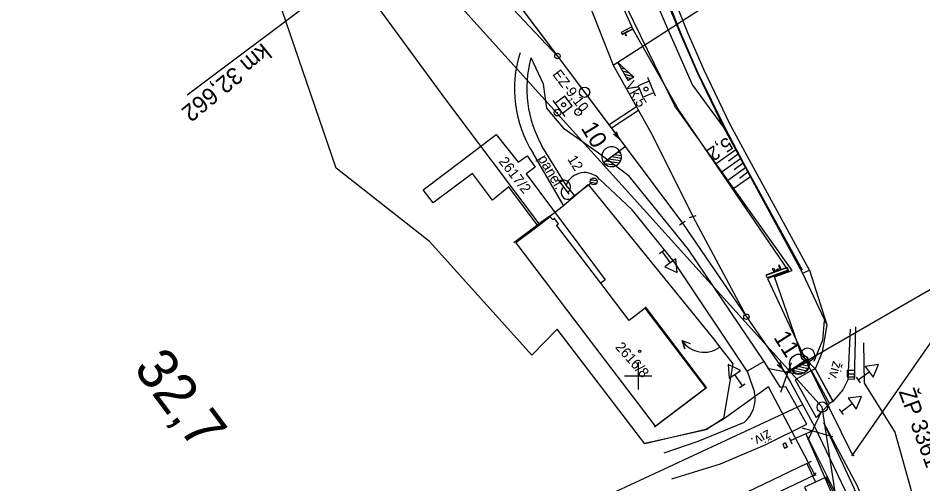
# Model space of a CAD drawing. Extents: x -804166 to -803706, y -1151030 to -1150147.
# Drawn here: x -803991 to -803858.2, y -1150515.9 to -1150447.5 of the extents above; entities that cross this region are included whole.
import ezdxf

# ---------------------------------------------------------------- set-up
doc = ezdxf.new("R2010")
doc.units = 0
for name, color, linetype in [('0381KM032-037P - Vrstva 1', 7, 'Continuous'), ('0381KM032-037P - Vrstva 12', 7, 'Continuous'), ('0381KM032-037P - Vrstva 13', 7, 'Continuous'), ('0381KM032-037P - Vrstva 17', 7, 'Continuous'), ('0381KM032-037P - Vrstva 19', 7, 'Continuous'), ('0381KM032-037P - Vrstva 2', 7, 'Continuous'), ('0381KM032-037P - Vrstva 23', 7, 'Continuous'), ('0381KM032-037P - Vrstva 25', 7, 'Continuous'), ('0381KM032-037P - Vrstva 27', 7, 'Continuous'), ('0381KM032-037P - Vrstva 3', 7, 'Continuous'), ('0381KM032-037P - Vrstva 4', 7, 'Continuous'), ('0381KM032-037P - Vrstva 43', 7, 'Continuous'), ('0381KM032-037P - Vrstva 48', 7, 'Continuous'), ('0381KM032-037P - Vrstva 49', 7, 'Continuous'), ('0381KM032-037P - Vrstva 5', 7, 'Continuous'), ('0381KM032-037P - Vrstva 51', 7, 'Continuous'), ('0381KM032-037P - Vrstva 55', 7, 'Continuous'), ('0381KM032-037P - Vrstva 57', 7, 'Continuous'), ('0381KM032-037P - Vrstva 59', 7, 'Continuous'), ('0381KM032-037P - Vrstva 6', 7, 'Continuous'), ('0381KM032-037P - Vrstva 7', 7, 'Continuous'), ('hran DP - hran DP', 7, 'Continuous'), ('krizky_1000 - Vrstva 1', 7, 'Continuous'), ('vyt_sit - polygon', 7, 'Continuous'), ('vyt_sit - stávající', 7, 'Continuous')]:
    doc.layers.add(name, color=color, linetype=linetype)

msp = doc.modelspace()

# ---------------------------------------------------------------- linework, layer by layer
at = {"layer": '0381KM032-037P - Vrstva 1'}
msp.add_line((-803901.9, -1150466.33), (-803893.52, -1150477.59), dxfattribs=at)
for points in [[(-804011.14, -1150262.39), (-804005.45, -1150273.41), (-803998.73, -1150284.85), (-803991.51, -1150295.63), (-803978.8, -1150312.77), (-803963.69, -1150332.99), (-803952.21, -1150348.36), (-803946.3, -1150356.39), (-803941.6, -1150363.14), (-803936.71, -1150370.83), (-803932.05, -1150378.84), (-803927.78, -1150386.91), (-803924.06, -1150395.18), (-803920.62, -1150403.65), (-803918.06, -1150410.86), (-803915.07, -1150420.32), (-803912.96, -1150427.25), (-803910.49, -1150435.34), (-803907.33, -1150445.05), (-803903.67, -1150454.38), (-803897.94, -1150464.6), (-803891.97, -1150476.6)], [(-803975.62, -1150392.3), (-803939.47, -1150444.12), (-803928.27, -1150459.42), (-803914.53, -1150477.73)], [(-803921.85, -1150439.73), (-803911.86, -1150453.03), (-803902.83, -1150465.07), (-803901.9, -1150466.33)], [(-803923.25, -1150440.92), (-803911.86, -1150453.03), (-803902.83, -1150465.07), (-803901.9, -1150466.33)], [(-803891.97, -1150476.6), (-803884.11, -1150491.33), (-803878.84, -1150498.97), (-803878.44, -1150499.6)], [(-803893.52, -1150477.59), (-803884.11, -1150491.33), (-803878.84, -1150498.97), (-803878.44, -1150499.6)], [(-803878.44, -1150499.6), (-803877.66, -1150500.95), (-803874.07, -1150507.54)], [(-803874.07, -1150507.54), (-803869.67, -1150516.77), (-803865.8, -1150526.59), (-803862.65, -1150536.71)]]:
    msp.add_lwpolyline(points, dxfattribs=at)
at = {"layer": '0381KM032-037P - Vrstva 12'}
for q in [(-803878.79, -1150510.04), (-803878.4, -1150509.87), (-803878.14, -1150510.46)]:
    msp.add_line((-803878.39, -1150509.85), q, dxfattribs=at)
for points in [[(-803878.4, -1150509.87), (-803878.79, -1150510.05), (-803878.52, -1150510.62), (-803878.14, -1150510.45), (-803878.4, -1150509.87)], [(-803878.79, -1150510.05), (-803878.79, -1150510.04), (-803878.54, -1150510.62), (-803878.52, -1150510.62)], [(-803878.54, -1150510.62), (-803878.14, -1150510.46), (-803878.14, -1150510.45)]]:
    msp.add_lwpolyline(points, dxfattribs=at)
at = {"layer": '0381KM032-037P - Vrstva 13'}
msp.add_lwpolyline([(-803875.88, -1150484.91), (-803874.86, -1150484.5), (-803883.66, -1150468.35), (-803886.5, -1150463.09), (-803890.34, -1150455.1), (-803892.74, -1150449.64), (-803894.89, -1150444.21), (-803895.92, -1150441.28), (-803896.68, -1150438.64), (-803897.15, -1150435.87), (-803897.2, -1150433.43), (-803898.65, -1150433.26), (-803898.54, -1150435.86), (-803897.99, -1150438.86), (-803897.04, -1150441.74), (-803895.99, -1150444.53), (-803893.7, -1150450.06), (-803891.29, -1150455.54), (-803887.41, -1150463.6)], close=True, dxfattribs=at)
at = {"layer": '0381KM032-037P - Vrstva 17'}
for p, q in [((-803911.21, -1150475.17), (-803907.34, -1150471.9)), ((-803888.96, -1150494.57), (-803888.03, -1150495.78))]:
    msp.add_line(p, q, dxfattribs=at)
for points in [[(-803875.87, -1150484.46), (-803884.49, -1150468.8), (-803887.25, -1150463.57), (-803891.19, -1150455.53), (-803893.61, -1150450.03), (-803895.79, -1150444.44), (-803896.9, -1150441.76), (-803897.82, -1150438.89), (-803898.31, -1150435.88), (-803898.26, -1150432.78)], [(-803907.34, -1150471.9), (-803888.96, -1150494.57)], [(-803912.99, -1150476.53), (-803911.21, -1150475.17)], [(-803872.72, -1150491.9), (-803872.97, -1150494.74), (-803874.21, -1150497.92)], [(-803888.03, -1150495.78), (-803886.13, -1150498.24), (-803887.49, -1150506.28), (-803890.05, -1150507.93), (-803899.02, -1150509.95)]]:
    msp.add_lwpolyline(points, dxfattribs=at)
at = {"layer": '0381KM032-037P - Vrstva 19'}
for p, q in [((-803902.47, -1150449.51), (-803900.98, -1150448.74)), ((-803900.83, -1150449.07), (-803902.37, -1150449.82)), ((-803902.35, -1150449.88), (-803900.83, -1150449.07)), ((-803900.98, -1150448.74), (-803900.83, -1150449.07)), ((-803902.37, -1150449.82), (-803902.47, -1150449.51)), ((-803902.37, -1150449.82), (-803902.35, -1150449.88)), ((-803901.82, -1150450), (-803901.91, -1150449.7)), ((-803881.21, -1150485.2), (-803878.12, -1150484.1)), ((-803877.97, -1150484.47), (-803881.05, -1150485.62)), ((-803879.4, -1150483.82), (-803879.16, -1150484.36)), ((-803879.16, -1150484.36), (-803879.02, -1150484.39)), ((-803878.12, -1150484.1), (-803877.97, -1150484.47)), ((-803881.05, -1150485.62), (-803881.21, -1150485.2))]:
    msp.add_line(p, q, dxfattribs=at)
for points in [[(-803900.83, -1150449.07), (-803900.83, -1150449.07), (-803900.77, -1150449.2)], [(-803901.91, -1150449.7), (-803901.91, -1150449.66), (-803901.71, -1150450.07), (-803901.82, -1150450)], [(-803878.12, -1150484.1), (-803878.12, -1150484.1), (-803881.19, -1150485.17), (-803881.21, -1150485.2)], [(-803880.09, -1150484.18), (-803879.84, -1150484.69), (-803880.02, -1150484.66), (-803880.28, -1150484.3), (-803880.09, -1150484.18)], [(-803879.02, -1150484.39), (-803879.24, -1150483.75), (-803879.4, -1150483.82)]]:
    msp.add_lwpolyline(points, dxfattribs=at)
for centre, major_axis, ratio in [((-803901.56, -1150449.43), (0.129, 0.077), 0.428282), ((-803879.58, -1150484.39), (-0.127, -0.08), 0.380929)]:
    msp.add_ellipse(centre, major_axis=major_axis, ratio=ratio, dxfattribs=at)
at = {"layer": '0381KM032-037P - Vrstva 2'}
for p, q in [((-803921.85, -1150439.73), (-803911.86, -1150453.03)), ((-803905.08, -1150468.69), (-803901.9, -1150466.33)), ((-803905.08, -1150468.69), (-803902.73, -1150466.95)), ((-803902.45, -1150467.68), (-803903.5, -1150467.52)), ((-803902.55, -1150467.28), (-803903.07, -1150467.2)), ((-803905.08, -1150468.69), (-803905.08, -1150468.69)), ((-803903.2, -1150469.1), (-803904.95, -1150468.84)), ((-803902.8, -1150468.78), (-803904.8, -1150468.48)), ((-803902.58, -1150468.42), (-803904.37, -1150468.16)), ((-803902.47, -1150468.06), (-803903.93, -1150467.84)), ((-803878.44, -1150499.6), (-803834.82, -1150474.4)), ((-803892.45, -1150476.74), (-803891.49, -1150476.45)), ((-803891.97, -1150476.6), (-803884.11, -1150491.33)), ((-803893.09, -1150477.33), (-803893.95, -1150477.85)), ((-803877.57, -1150499.05), (-803875.11, -1150497.47)), ((-803876.32, -1150498.25), (-803874.91, -1150498.56)), ((-803875.87, -1150497.96), (-803874.88, -1150498.18)), ((-803875.43, -1150497.68), (-803874.96, -1150497.78)), ((-803877.58, -1150499.05), (-803878.44, -1150499.6)), ((-803877.57, -1150499.05), (-803877.57, -1150499.05)), ((-803877.51, -1150499.14), (-803875.65, -1150499.55)), ((-803877.22, -1150498.82), (-803875.27, -1150499.25)), ((-803876.77, -1150498.53), (-803875.04, -1150498.92))]:
    msp.add_line(p, q, dxfattribs=at)
for points in [[(-803923.25, -1150440.92), (-803911.86, -1150453.03), (-803901.9, -1150466.33)], [(-803903.62, -1150464.45), (-803902.83, -1150465.07), (-803903.2, -1150464.14)], [(-803893.52, -1150477.59), (-803884.11, -1150491.33), (-803878.84, -1150498.97), (-803878.44, -1150499.6)], [(-803879.6, -1150498.32), (-803878.84, -1150498.97), (-803879.17, -1150498.03)]]:
    msp.add_lwpolyline(points, dxfattribs=at)
for centre, radius in [((-803911.86, -1150453.03), 0.4), ((-803884.11, -1150491.33), 0.4), ((-803876.33, -1150498.26), 1.46)]:
    msp.add_circle(centre, radius, dxfattribs=at)
for centre, start, end in [((-803903.91, -1150467.82), 36.4057, 216.8752), ((-803903.91, -1150467.82), 216.4952, 36.456), ((-803876.34, -1150498.26), 212.5372, 32.498)]:
    msp.add_arc(centre, 1.46, start, end, dxfattribs=at)
at = {"layer": '0381KM032-037P - Vrstva 23'}
for p, q in [((-803893.15, -1150496.04), (-803893.53, -1150494.83)), ((-803893.53, -1150494.83), (-803893.15, -1150496.04)), ((-803893.53, -1150494.83), (-803892.38, -1150495.23))]:
    msp.add_line(p, q, dxfattribs=at)
for points in [[(-803912.99, -1150476.53), (-803913.94, -1150477.26), (-803918.26, -1150480.47)], [(-803897.63, -1150507.47), (-803890, -1150501.72), (-803898.95, -1150489.89)]]:
    msp.add_lwpolyline(points, dxfattribs=at)
msp.add_arc((-803890.34, -1150492.71), 3.83, 213.4897, 307.0096, dxfattribs=at)
at = {"layer": '0381KM032-037P - Vrstva 25'}
for p, q in [((-803910.15, -1150473.3), (-803911.72, -1150471.23)), ((-803906.94, -1150471.75), (-803909.73, -1150473.86)), ((-803906.13, -1150471.74), (-803907.01, -1150471.62)), ((-803906.05, -1150471.38), (-803906.99, -1150471.24))]:
    msp.add_line(p, q, dxfattribs=at)
msp.add_circle((-803906.54, -1150471.45), 0.5, dxfattribs=at)
msp.add_circle((-803906.54, -1150471.45), 0.5, dxfattribs=at)
for centre, start, end in [((-803910.93, -1150472.26), 306.3777, 127.7829), ((-803910.33, -1150473.06), 127.0803, 307.0803)]:
    msp.add_arc(centre, 1, start, end, dxfattribs=at)
at = {"layer": '0381KM032-037P - Vrstva 27'}
msp.add_line((-803908.87, -1150461.27), (-803908.77, -1150461.27), dxfattribs=at)
msp.add_circle((-803908.82, -1150461.27), 0.5, dxfattribs=at)
at = {"layer": '0381KM032-037P - Vrstva 3'}
for p, q in [((-803903.67, -1150454.38), (-803871.13, -1150433.38)), ((-803902.8, -1150454.28), (-803902.57, -1150454.35)), ((-803902.55, -1150454.75), (-803901.95, -1150454.91)), ((-803902.29, -1150455.21), (-803901.33, -1150455.48)), ((-803902.03, -1150455.67), (-803900.71, -1150456.04)), ((-803901.77, -1150456.13), (-803901.03, -1150456.34)), ((-803901.51, -1150456.6), (-803901.49, -1150456.6)), ((-803898.37, -1150456.73), (-803900.01, -1150457.42)), ((-803897.46, -1150458.91), (-803898.6, -1150456.19)), ((-803900.01, -1150457.42), (-803899.32, -1150459.05)), ((-803899.32, -1150459.05), (-803897.69, -1150458.37)), ((-803912.55, -1150459.55), (-803910.76, -1150461.9)), ((-803910.78, -1150458.95), (-803912.19, -1150460.02)), ((-803909.7, -1150460.36), (-803910.78, -1150458.95)), ((-803911.12, -1150461.43), (-803909.7, -1150460.36))]:
    msp.add_line(p, q, dxfattribs=at)
msp.add_lwpolyline([(-803902.97, -1150453.99), (-803900.63, -1150456.12), (-803901.5, -1150456.61), (-803902.97, -1150453.99)], dxfattribs=at)
for centre in [(-803898.85, -1150457.89), (-803910.95, -1150460.19)]:
    msp.add_circle(centre, 0.296, dxfattribs=at)
at = {"layer": '0381KM032-037P - Vrstva 4'}
for p, q in [((-803879.07, -1150502.39), (-803877.49, -1150498.06)), ((-803874.95, -1150497.78), (-803878, -1150499.5)), ((-803874.7, -1150498.22), (-803875.19, -1150497.35)), ((-803876.51, -1150499.81), (-803881.03, -1150498.91)), ((-803877.66, -1150500.95), (-803874.07, -1150507.54)), ((-803875.88, -1150504.25), (-803939.78, -1150533.94)), ((-803873.14, -1150505.27), (-803875.09, -1150509.46)), ((-803877.64, -1150509.52), (-803874.45, -1150508.07)), ((-803875.92, -1150507.64), (-803871.49, -1150508.91)), ((-803877.85, -1150509.06), (-803877.43, -1150509.98))]:
    msp.add_line(p, q, dxfattribs=at)
for points in [[(-803872.78, -1150506.88), (-803867.87, -1150516.17), (-803864, -1150525.68), (-803860.6, -1150536.29), (-803857.96, -1150547.89), (-803856.11, -1150558.65), (-803855.01, -1150569.42), (-803855.01, -1150580.14), (-803855.68, -1150591.14), (-803857.11, -1150602.1)], [(-803872.78, -1150506.88), (-803868.42, -1150516.34), (-803864.49, -1150525.92), (-803861.19, -1150536.4), (-803858.42, -1150547.95), (-803856.72, -1150558.77), (-803855.71, -1150569.46), (-803855.71, -1150580.04), (-803856.44, -1150591.04), (-803858.02, -1150602.01)], [(-803875.39, -1150508.51), (-803870.94, -1150517.43), (-803867.28, -1150527.02), (-803864.07, -1150537.14), (-803861.55, -1150548.3), (-803859.95, -1150558.94), (-803859.25, -1150569.65), (-803859.08, -1150579.87)], [(-803875.39, -1150508.51), (-803871.45, -1150517.68), (-803867.83, -1150527.24), (-803864.66, -1150537.29), (-803862.15, -1150548.38), (-803860.59, -1150559), (-803859.92, -1150569.63), (-803859.95, -1150579.8), (-803860.5, -1150590.58), (-803862.04, -1150601.17)]]:
    msp.add_lwpolyline(points, dxfattribs=at)
at = {"layer": '0381KM032-037P - Vrstva 43'}
for points in [[(-803871.41, -1150503.77), (-803871.94, -1150504.07), (-803874.58, -1150499.23), (-803874.04, -1150498.95), (-803871.41, -1150503.77)], [(-803874.57, -1150499.23), (-803874.03, -1150498.95), (-803871.39, -1150503.78), (-803871.94, -1150504.09), (-803874.57, -1150499.23)], [(-803869.26, -1150499.69), (-803869.26, -1150499.19), (-803868.26, -1150499.19), (-803868.26, -1150500.19), (-803869.26, -1150500.19), (-803869.26, -1150499.69), (-803868.26, -1150499.69)]]:
    msp.add_lwpolyline(points, dxfattribs=at)
msp.add_circle((-803875.13, -1150496.91), 1, dxfattribs=at)
at = {"layer": '0381KM032-037P - Vrstva 48'}
for p, q in [((-803885.69, -1150466.79), (-803888.57, -1150468.84)), ((-803885.33, -1150467.46), (-803886.73, -1150468.45)), ((-803884.97, -1150468.12), (-803887.7, -1150470.06)), ((-803884.61, -1150468.79), (-803885.94, -1150469.73)), ((-803884.25, -1150469.45), (-803886.83, -1150471.29)), ((-803883.89, -1150470.11), (-803885.14, -1150471.01)), ((-803883.53, -1150470.78), (-803885.96, -1150472.51))]:
    msp.add_line(p, q, dxfattribs=at)
at = {"layer": '0381KM032-037P - Vrstva 49'}
for p, q in [((-803880.01, -1150485.46), (-803877.42, -1150484.53)), ((-803875.88, -1150484.91), (-803872.32, -1150492.5)), ((-803868.36, -1150511.37), (-803868.71, -1150511.73)), ((-803868.71, -1150511.37), (-803868.36, -1150511.73)), ((-803873.9, -1150514.27), (-803874.25, -1150514.62)), ((-803874.25, -1150514.27), (-803873.9, -1150514.62))]:
    msp.add_line(p, q, dxfattribs=at)
for points in [[(-803920.94, -1150376.21), (-803910.02, -1150390.51), (-803912.55, -1150396.06), (-803903.87, -1150412.95), (-803903.68, -1150418.64), (-803901.42, -1150428.97), (-803900.54, -1150437.64), (-803895.89, -1150448.56), (-803892.01, -1150457.3), (-803887.41, -1150463.6), (-803875.88, -1150484.91), (-803874.86, -1150484.5), (-803872.32, -1150492.5), (-803873, -1150496.55), (-803874.04, -1150498.95)], [(-803877.42, -1150484.53), (-803894.61, -1150460.33), (-803907.65, -1150433.62), (-803908.81, -1150430.91)], [(-803874.04, -1150498.95), (-803875.99, -1150497.05), (-803878.61, -1150489.36), (-803880.01, -1150485.46)], [(-803866.91, -1150495.14), (-803866.85, -1150501.09), (-803862.34, -1150508.28), (-803859.07, -1150519.98)]]:
    msp.add_lwpolyline(points, dxfattribs=at)
at = {"layer": '0381KM032-037P - Vrstva 5'}
for p, q in [((-803875.27, -1150512.9), (-803915.96, -1150532.37)), ((-803874.59, -1150512.58), (-803875.94, -1150513.22))]:
    msp.add_line(p, q, dxfattribs=at)
msp.add_lwpolyline([(-803875.27, -1150512.9), (-803873.99, -1150515.61), (-803875.58, -1150516.36), (-803874.51, -1150518.62), (-803871.34, -1150517.13), (-803872.41, -1150514.87), (-803873.99, -1150515.61)], dxfattribs=at)
at = {"layer": '0381KM032-037P - Vrstva 51'}
for p, q in [((-803915.74, -1150453.31), (-803915.72, -1150453.29)), ((-803915.45, -1150467.28), (-803911.05, -1150474.87)), ((-803900.89, -1150475.61), (-803905.68, -1150471.14)), ((-803896.07, -1150481.49), (-803896.87, -1150482.08)), ((-803881.52, -1150497.91), (-803884.01, -1150499.3)), ((-803879.11, -1150501.71), (-803881.52, -1150497.91)), ((-803884.01, -1150499.3), (-803882.94, -1150502.42)), ((-803868, -1150500.21), (-803867.4, -1150501.01)), ((-803885.13, -1150501.74), (-803884.3, -1150501.18)), ((-803870.52, -1150504.88), (-803869.93, -1150505.68))]:
    msp.add_line(p, q, dxfattribs=at)
for points in [[(-803881.52, -1150497.91), (-803892.6, -1150481.46), (-803901.35, -1150470.69), (-803906.02, -1150467.13), (-803910.84, -1150463.75), (-803913.43, -1150460.67), (-803913.91, -1150457.14), (-803915.72, -1150453.29)], [(-803909.32, -1150473.55), (-803910.58, -1150471.98), (-803914.08, -1150466.31)], [(-803884.01, -1150499.3), (-803894.74, -1150483.24), (-803900.89, -1150475.61)], [(-803896.47, -1150481.79), (-803895.29, -1150483.4), (-803896.1, -1150483.99), (-803894.26, -1150484.82), (-803894.48, -1150482.81), (-803895.29, -1150483.4)], [(-803872.32, -1150492.5), (-803873, -1150496.55), (-803874.04, -1150498.95), (-803874.58, -1150499.23), (-803876.98, -1150500.59), (-803873.89, -1150506.13)], [(-803868.09, -1150492.82), (-803868.28, -1150500.56), (-803869.18, -1150500.5), (-803868.82, -1150493.14)], [(-803884.71, -1150501.46), (-803885.82, -1150499.79), (-803884.98, -1150499.24), (-803886.78, -1150498.33), (-803886.65, -1150500.34), (-803885.82, -1150499.79)], [(-803867.7, -1150500.61), (-803866.11, -1150499.41), (-803865.5, -1150500.2), (-803864.71, -1150498.35), (-803866.71, -1150498.61), (-803866.11, -1150499.41)], [(-803869.18, -1150500.5), (-803869.95, -1150502.07), (-803871.41, -1150503.77), (-803871.94, -1150504.07), (-803873.89, -1150506.13)], [(-803875.27, -1150507.1), (-803878.32, -1150501.63), (-803879.11, -1150501.71)], [(-803870.22, -1150505.28), (-803868.61, -1150504.09), (-803868.02, -1150504.9), (-803867.2, -1150503.06), (-803869.2, -1150503.29), (-803868.61, -1150504.09)], [(-803884.45, -1150506.84), (-803891.24, -1150509.65), (-803896.22, -1150511.35)], [(-803895.07, -1150515.15), (-803887.92, -1150512.92), (-803881.36, -1150510.15), (-803875.27, -1150507.1)]]:
    msp.add_lwpolyline(points, dxfattribs=at)
for centre, major_axis, ratio, start_param, end_param in [((-803900.85, -1150457.93), (3.99, -16.88), 0.999168, 4.166515, 5.049488), ((-803899.46, -1150457.84), (3.31, -16.59), 0.999136, 4.244568, 5.04061), ((-803907.87, -1150473.07), (-1.91, 2.21), 0.999734, 4.72036, 6.75861), ((-803887.41, -1150503.35), (0.39, 4.56), 0.996998, 3.930903, 5.00319)]:
    msp.add_ellipse(centre, major_axis=major_axis, ratio=ratio, start_param=start_param, end_param=end_param, dxfattribs=at)
at = {"layer": '0381KM032-037P - Vrstva 55'}
for points in [[(-803914.71, -1150478.01), (-803919.01, -1150472.26), (-803921.41, -1150474.2), (-803924.33, -1150470.27), (-803930.11, -1150474.6), (-803931.57, -1150472.66), (-803925.79, -1150468.33), (-803920.83, -1150464.56), (-803917.63, -1150468.64), (-803916.3, -1150467.69), (-803915.12, -1150469.35), (-803916.46, -1150470.34), (-803904.84, -1150485.91), (-803905.5, -1150486.41)], [(-803901.34, -1150491.89), (-803905.5, -1150486.41), (-803911.98, -1150477.87), (-803911.71, -1150477.67), (-803912.3, -1150476.91), (-803912.56, -1150477.11), (-803912.92, -1150476.64), (-803914.71, -1150478.01), (-803917.95, -1150480.48), (-803906.42, -1150495.69), (-803897.53, -1150507.41), (-803890.06, -1150501.75), (-803898.96, -1150490.08), (-803901.34, -1150491.89)]]:
    msp.add_lwpolyline(points, dxfattribs=at)
at = {"layer": '0381KM032-037P - Vrstva 59'}
msp.add_circle((-803899.79, -1150496.4), 0.175, dxfattribs=at)
at = {"layer": '0381KM032-037P - Vrstva 6'}
msp.add_line((-803935.82, -1150435.93), (-803966.23, -1150458.78), dxfattribs=at)
at = {"layer": '0381KM032-037P - Vrstva 7'}
for p, q in [((-803900.24, -1150460.49), (-803904.29, -1150463.13)), ((-803899.95, -1150461.02), (-803903.93, -1150463.61)), ((-803911.9, -1150461.33), (-803911.8, -1150461.33))]:
    msp.add_line(p, q, dxfattribs=at)
for centre, radius in [((-803907.87, -1150458.35), 0.75), ((-803911.85, -1150461.33), 0.5)]:
    msp.add_circle(centre, radius, dxfattribs=at)
at = {"layer": 'hran DP - hran DP'}
for p, q in [((-803907.15, -1150435.03), (-803900.76, -1150449.16)), ((-803944.36, -1150469.51), (-803953.58, -1150442.45)), ((-803900.76, -1150449.16), (-803893.94, -1150461.19)), ((-803893.94, -1150461.19), (-803877.95, -1150484.62)), ((-803930.65, -1150480.27), (-803944.36, -1150469.51)), ((-803915.62, -1150496.95), (-803930.65, -1150480.27)), ((-803877.95, -1150484.62), (-803881.02, -1150485.69)), ((-803881.02, -1150485.69), (-803875.42, -1150497.74)), ((-803911.88, -1150493.16), (-803915.62, -1150496.95)), ((-803899.02, -1150510.01), (-803911.88, -1150493.16)), ((-803868.53, -1150511.63), (-803856.45, -1150494.27)), ((-803875.42, -1150497.74), (-803868.53, -1150511.63)), ((-803880.9, -1150501.6), (-803887.46, -1150506.35)), ((-803874.06, -1150514.53), (-803880.9, -1150501.6)), ((-803887.46, -1150506.35), (-803890.08, -1150507.89)), ((-803890.08, -1150507.89), (-803899.02, -1150510.01)), ((-803881.88, -1150518.24), (-803874.06, -1150514.53))]:
    msp.add_line(p, q, dxfattribs=at)
at = {"layer": 'krizky_1000 - Vrstva 1'}
for points in [[(-803900, -1150498), (-803900, -1150502)], [(-803902, -1150500), (-803898, -1150500)]]:
    msp.add_lwpolyline(points, dxfattribs=at)
at = {"layer": 'vyt_sit - polygon'}
for p, q in [((-803872.98, -1150504.59), (-803955.93, -1150412.63)), ((-803857.35, -1150608.08), (-803872.98, -1150504.59))]:
    msp.add_line(p, q, dxfattribs=at)
at = {"layer": 'vyt_sit - stávající'}
msp.add_line((-803873.03, -1150504.59), (-803872.93, -1150504.59), dxfattribs=at)
msp.add_circle((-803872.98, -1150504.59), 0.756, dxfattribs=at)

# ---------------------------------------------------------------- texts
at = {"layer": '0381KM032-037P - Vrstva 2'}
for s, rotation, p in [('10', 301.4756, (-803908.48, -1150463.61)), ('11', 302.5176, (-803880.21, -1150494.37))]:
    msp.add_text(s, height=2.5, rotation=rotation, dxfattribs=at).set_placement(p)
at = {"layer": '0381KM032-037P - Vrstva 25'}
msp.add_text('12', height=1.5, rotation=302.0803, dxfattribs=at).set_placement((-803910.44, -1150468.17))
at = {"layer": '0381KM032-037P - Vrstva 3'}
for s, rotation, p in [('EZ-9,10', 307.2491, (-803912.66, -1150455.74)), ('Vk.5', 299.2898, (-803901.94, -1150457.22))]:
    msp.add_text(s, height=1.5, rotation=rotation, dxfattribs=at).set_placement(p)
at = {"layer": '0381KM032-037P - Vrstva 48'}
msp.add_text('5,2', height=2, rotation=213.4162, dxfattribs=at).set_placement((-803886.96, -1150464.84))
at = {"layer": '0381KM032-037P - Vrstva 51'}
for s, rotation, p in [('panel.', 300.0966, (-803914.77, -1150468.07)), ('živ.', 254.3904, (-803871.38, -1150497.73)), ('živ.', 207.9481, (-803880.96, -1150507.85))]:
    msp.add_text(s, height=1.5, rotation=rotation, dxfattribs=at).set_placement(p)
at = {"layer": '0381KM032-037P - Vrstva 57'}
for s, rotation, p in [('2617/2', 308.0366, (-803920.56, -1150468.55)), ('2616/8', 311.4623, (-803903.45, -1150495.84))]:
    msp.add_text(s, height=1.5, rotation=rotation, dxfattribs=at).set_placement(p)
at = {"layer": '0381KM032-037P - Vrstva 6'}
msp.add_text('km 32,662', height=2.5, rotation=219.5182, dxfattribs=at).set_placement((-803955.2, -1150451.01))
at = {"layer": '0381KM032-037P - Vrstva 7'}
msp.add_text('32,7', height=6, rotation=306.901, dxfattribs=at).set_placement((-803974.22, -1150498.93))
at = {"layer": 'vyt_sit - stávající'}
msp.add_text('ŽP 3361', height=2.4, rotation=290, dxfattribs=at).set_placement((-803861.8, -1150502.29))

doc.saveas('drawing.dxf')
